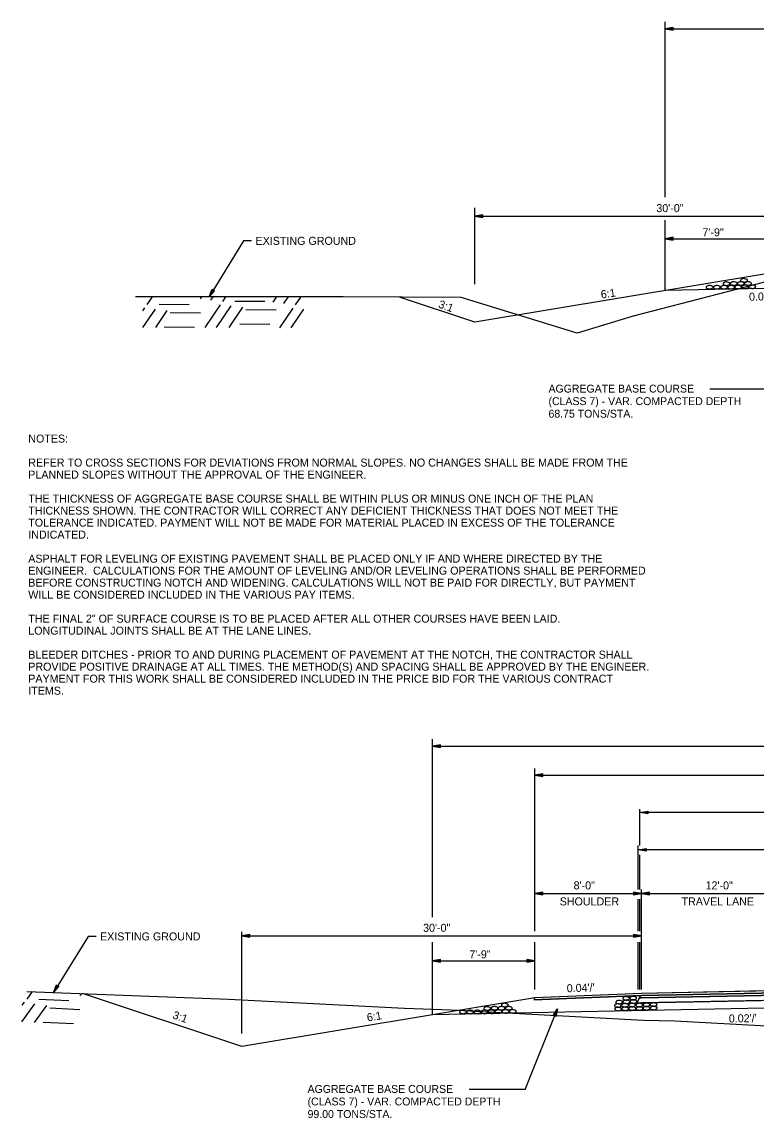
# Model space of a CAD drawing. Extents: x 1461846 to 1462006, y 1686171 to 1686805.
# Drawn here: x 1461850.2 to 1461905.3, y 1686719.1 to 1686801.3 of the extents above; entities that cross this region are included whole.
import ezdxf

# ---------------------------------------------------------------- set-up
doc = ezdxf.new("R2010")
doc.units = 0
for name, color, linetype in [('1', 7, 'Continuous'), ('19', 7, 'Continuous'), ('20', 7, 'Continuous'), ('R_Draft', 7, 'Continuous')]:
    doc.layers.add(name, color=color, linetype=linetype)

# ---------------------------------------------------------------- blocks, each defined once
blk = doc.blocks.new('ROCKS')
at = {"layer": '1'}
blk.add_spline([(0.013, 0.06), (0.053, 0.053), (0.107, 0.033), (0.133, 0.013), (0.133, -0.007), (0.12, -0.033), (0.107, -0.04), (0.073, -0.053), (0.033, -0.067), (0.013, -0.067), (-0.02, -0.06), (-0.06, -0.053), (-0.087, -0.047), (-0.113, -0.02), (-0.113, -0.007), (-0.107, 0.02), (-0.087, 0.033), (-0.067, 0.047), (-0.033, 0.053), (-0.02, 0.06), (0.013, 0.06)], degree=3, dxfattribs=at)

msp = doc.modelspace()

# ---------------------------------------------------------------- linework, layer by layer
at = {"layer": '19'}
for p, q in [((1461898.458, 1686788.158), (1461898.458, 1686801.288)), ((1461899.058, 1686800.872), (1461898.458, 1686800.767)), ((1461898.458, 1686800.767), (1461953.889, 1686800.767)), ((1461898.458, 1686800.767), (1461899.058, 1686800.662)), ((1461899.058, 1686800.817), (1461898.618, 1686800.782)), ((1461898.618, 1686800.752), (1461899.058, 1686800.712)), ((1461899.058, 1686800.662), (1461899.058, 1686800.872)), ((1461884.774, 1686786.831), (1461884.174, 1686786.726)), ((1461884.174, 1686786.726), (1461914.174, 1686786.726)), ((1461884.174, 1686786.726), (1461884.774, 1686786.621)), ((1461884.774, 1686786.776), (1461884.334, 1686786.741)), ((1461884.334, 1686786.711), (1461884.774, 1686786.671)), ((1461884.774, 1686786.621), (1461884.774, 1686786.831)), ((1461898.458, 1686781.149), (1461898.458, 1686786.426)), ((1461906.174, 1686782.435), (1461884.174, 1686778.769)), ((1461864.232, 1686780.674), (1461864.455, 1686781.241)), ((1461864.633, 1686781.131), (1461864.232, 1686780.674)), ((1461864.305, 1686780.815), (1461864.498, 1686781.209)), ((1461864.592, 1686781.152), (1461864.328, 1686780.804)), ((1461864.455, 1686781.241), (1461864.633, 1686781.131)), ((1461910.591, 1686781.392), (1461898.458, 1686781.149)), ((1461859.589, 1686780.092), (1461859.982, 1686780.674)), ((1461860.478, 1686780.129), (1461862.738, 1686780.103)), ((1461863.576, 1686780.517), (1461863.682, 1686780.667)), ((1461863.923, 1686778.369), (1461865.079, 1686780.087)), ((1461864.37, 1686780.423), (1461864.537, 1686780.667)), ((1461864.777, 1686778.369), (1461865.873, 1686779.994)), ((1461865.265, 1686780.329), (1461865.492, 1686780.667)), ((1461866.153, 1686780.356), (1461868.414, 1686780.34)), ((1461869.029, 1686780.265), (1461869.292, 1686780.659)), ((1461869.824, 1686780.171), (1461870.157, 1686780.659)), ((1461870.719, 1686780.077), (1461871.101, 1686780.65)), ((1461859.248, 1686779.625), (1461859.403, 1686779.85)), ((1461859.268, 1686778.376), (1461860.197, 1686779.757)), ((1461860.223, 1686778.376), (1461861.092, 1686779.662)), ((1461861.316, 1686779.498), (1461863.576, 1686779.471)), ((1461865.733, 1686778.369), (1461866.768, 1686779.899)), ((1461866.982, 1686779.726), (1461869.252, 1686779.708)), ((1461869.533, 1686778.361), (1461870.532, 1686779.835)), ((1461870.387, 1686778.362), (1461871.327, 1686779.741)), ((1461860.861, 1686778.42), (1461863.132, 1686778.402)), ((1461866.537, 1686778.657), (1461868.797, 1686778.63)), ((1461906.015, 1686773.763), (1461901.805, 1686773.763)), ((1461880.979, 1686734.152), (1461880.979, 1686747.499)), ((1461881.579, 1686747.084), (1461880.979, 1686746.979)), ((1461881.579, 1686746.874), (1461881.579, 1686747.084)), ((1461880.979, 1686746.979), (1461971.391, 1686746.979)), ((1461880.979, 1686746.979), (1461881.579, 1686746.874)), ((1461881.579, 1686747.029), (1461881.139, 1686746.994)), ((1461881.139, 1686746.964), (1461881.579, 1686746.924)), ((1461888.675, 1686733.114), (1461888.675, 1686745.306)), ((1461889.275, 1686744.911), (1461888.675, 1686744.806)), ((1461888.675, 1686744.806), (1461963.675, 1686744.806)), ((1461888.675, 1686744.806), (1461889.275, 1686744.701)), ((1461889.275, 1686744.856), (1461888.835, 1686744.821)), ((1461888.835, 1686744.791), (1461889.275, 1686744.751)), ((1461889.275, 1686744.701), (1461889.275, 1686744.911)), ((1461880.979, 1686726.84), (1461880.979, 1686732.284)), ((1461888.675, 1686728.743), (1461888.675, 1686732.284)), ((1461850.568, 1686728.011), (1461850.982, 1686728.578)), ((1461854.567, 1686728.292), (1461854.679, 1686728.437)), ((1461896.59, 1686728.273), (1461896.313, 1686727.72)), ((1461850.185, 1686726.308), (1461851.164, 1686727.654)), ((1461850.21, 1686727.557), (1461850.373, 1686727.776)), ((1461851.139, 1686726.273), (1461852.055, 1686727.527)), ((1461851.457, 1686728.016), (1461853.715, 1686727.908)), ((1461852.273, 1686727.355), (1461854.53, 1686727.246)), ((1461888.675, 1686728.123), (1461888.59, 1686727.953)), ((1461896.505, 1686728.103), (1461896.313, 1686727.72)), ((1461887.939, 1686721.25), (1461890.362, 1686727.3)), ((1461890.043, 1686726.783), (1461890.362, 1686727.3)), ((1461890.236, 1686726.704), (1461890.043, 1686726.783)), ((1461890.089, 1686726.765), (1461890.288, 1686727.158)), ((1461890.315, 1686727.148), (1461890.188, 1686726.727)), ((1461890.362, 1686727.3), (1461890.236, 1686726.704)), ((1461851.778, 1686726.294), (1461854.047, 1686726.194)), ((1461887.939, 1686721.25), (1461883.729, 1686721.25))]:
    msp.add_line(p, q, dxfattribs=at)
for points in [[(1461867.414, 1686784.873), (1461866.814, 1686784.873), (1461864.232, 1686780.674)], [(1461896.313, 1686727.72), (1461896.675, 1686727.734), (1461926.175, 1686728.324), (1461955.675, 1686727.734), (1461964.036, 1686727.4)], [(1461963.845, 1686727.783), (1461955.675, 1686728.109), (1461926.175, 1686728.699), (1461896.675, 1686728.109), (1461896.505, 1686728.103)]]:
    msp.add_lwpolyline(points, dxfattribs=at)
for points in [[(1461888.59, 1686727.953), (1461896.675, 1686728.276), (1461926.175, 1686728.866), (1461955.675, 1686728.276), (1461963.76, 1686727.953), (1461963.675, 1686728.123), (1461955.675, 1686728.443), (1461926.175, 1686729.033), (1461896.675, 1686728.443), (1461888.675, 1686728.123)], [(1461896.505, 1686728.103), (1461896.674, 1686728.109), (1461926.174, 1686728.699), (1461955.674, 1686728.109), (1461963.845, 1686727.783), (1461963.76, 1686727.953), (1461955.674, 1686728.276), (1461926.174, 1686728.866), (1461896.674, 1686728.276), (1461896.59, 1686728.273)]]:
    msp.add_lwpolyline(points, close=True, dxfattribs=at)
at = {"layer": '20'}
for p, q in [((1461884.174, 1686781.616), (1461884.174, 1686787.36)), ((1461899.058, 1686785.137), (1461898.458, 1686785.032)), ((1461898.458, 1686785.032), (1461906.174, 1686785.032)), ((1461898.458, 1686785.032), (1461899.058, 1686784.927)), ((1461899.058, 1686785.082), (1461898.618, 1686785.047)), ((1461898.618, 1686785.017), (1461899.058, 1686784.977)), ((1461899.058, 1686784.927), (1461899.058, 1686785.137)), ((1461896.545, 1686739.532), (1461896.545, 1686742.261)), ((1461896.545, 1686742.006), (1461897.145, 1686742.111)), ((1461897.145, 1686741.901), (1461896.545, 1686742.006)), ((1461963.801, 1686742.006), (1461896.545, 1686742.006)), ((1461896.705, 1686742.021), (1461897.145, 1686742.056)), ((1461897.145, 1686741.951), (1461896.705, 1686741.991)), ((1461897.145, 1686742.111), (1461897.145, 1686741.901)), ((1461896.413, 1686736.243), (1461896.413, 1686739.532)), ((1461896.413, 1686739.206), (1461897.013, 1686739.311)), ((1461963.933, 1686739.206), (1461896.413, 1686739.206)), ((1461897.013, 1686739.101), (1461896.413, 1686739.206)), ((1461896.545, 1686736.243), (1461896.545, 1686738.844)), ((1461896.573, 1686739.221), (1461897.013, 1686739.256)), ((1461897.013, 1686739.151), (1461896.573, 1686739.191)), ((1461897.013, 1686739.311), (1461897.013, 1686739.101)), ((1461896.413, 1686733.114), (1461896.413, 1686735.518)), ((1461896.545, 1686733.114), (1461896.545, 1686735.518)), ((1461896.413, 1686728.743), (1461896.413, 1686732.284)), ((1461896.545, 1686728.743), (1461896.545, 1686732.284)), ((1461881.579, 1686730.998), (1461880.979, 1686730.894)), ((1461880.979, 1686730.894), (1461888.675, 1686730.894)), ((1461880.979, 1686730.894), (1461881.579, 1686730.788)), ((1461881.579, 1686730.943), (1461881.139, 1686730.908)), ((1461881.139, 1686730.878), (1461881.579, 1686730.838)), ((1461881.579, 1686730.788), (1461881.579, 1686730.998)), ((1461888.075, 1686730.999), (1461888.075, 1686730.789)), ((1461888.675, 1686730.894), (1461888.075, 1686730.999)), ((1461888.515, 1686730.909), (1461888.075, 1686730.944)), ((1461888.075, 1686730.789), (1461888.675, 1686730.894)), ((1461888.075, 1686730.839), (1461888.515, 1686730.879))]:
    msp.add_line(p, q, dxfattribs=at)
at = {"layer": 'R_Draft'}
for p, q in [((1461884.174, 1686778.769), (1461878.518, 1686780.654)), ((1461889.275, 1686736.048), (1461888.675, 1686735.943)), ((1461888.675, 1686735.943), (1461896.675, 1686735.943)), ((1461888.675, 1686735.943), (1461889.275, 1686735.838)), ((1461889.275, 1686735.993), (1461888.835, 1686735.958)), ((1461888.835, 1686735.928), (1461889.275, 1686735.888)), ((1461889.275, 1686735.838), (1461889.275, 1686736.048)), ((1461896.075, 1686736.048), (1461896.075, 1686735.838)), ((1461896.675, 1686735.943), (1461896.075, 1686736.048)), ((1461896.515, 1686735.958), (1461896.075, 1686735.993)), ((1461896.075, 1686735.838), (1461896.675, 1686735.943)), ((1461896.075, 1686735.888), (1461896.515, 1686735.928)), ((1461896.675, 1686728.743), (1461896.675, 1686736.243)), ((1461897.275, 1686736.048), (1461896.675, 1686735.943)), ((1461897.275, 1686736.048), (1461896.675, 1686735.943)), ((1461896.675, 1686735.943), (1461897.275, 1686735.838)), ((1461896.675, 1686735.943), (1461908.675, 1686735.943)), ((1461896.675, 1686735.943), (1461897.275, 1686735.838)), ((1461897.275, 1686735.993), (1461896.835, 1686735.958)), ((1461897.275, 1686735.993), (1461896.835, 1686735.958)), ((1461896.835, 1686735.928), (1461897.275, 1686735.888)), ((1461896.835, 1686735.928), (1461897.275, 1686735.888)), ((1461897.275, 1686735.838), (1461897.275, 1686736.048)), ((1461897.275, 1686735.838), (1461897.275, 1686736.048)), ((1461866.675, 1686725.439), (1461866.675, 1686733.064)), ((1461867.275, 1686732.869), (1461866.675, 1686732.764)), ((1461866.675, 1686732.764), (1461896.675, 1686732.764)), ((1461866.675, 1686732.764), (1461867.275, 1686732.659)), ((1461867.275, 1686732.814), (1461866.835, 1686732.779)), ((1461866.835, 1686732.749), (1461867.275, 1686732.709)), ((1461867.275, 1686732.659), (1461867.275, 1686732.869)), ((1461896.075, 1686732.869), (1461896.075, 1686732.659)), ((1461896.675, 1686732.764), (1461896.075, 1686732.869)), ((1461896.515, 1686732.779), (1461896.075, 1686732.814)), ((1461896.075, 1686732.659), (1461896.675, 1686732.764)), ((1461896.075, 1686732.709), (1461896.515, 1686732.749)), ((1461852.562, 1686728.518), (1461852.786, 1686729.084)), ((1461852.963, 1686728.975), (1461852.562, 1686728.518)), ((1461852.636, 1686728.659), (1461852.829, 1686729.052)), ((1461852.923, 1686728.996), (1461852.659, 1686728.647)), ((1461852.786, 1686729.084), (1461852.963, 1686728.975)), ((1461926.175, 1686729.033), (1461896.675, 1686728.443)), ((1461866.675, 1686724.456), (1461854.74, 1686728.434)), ((1461896.675, 1686728.276), (1461888.59, 1686727.953)), ((1461896.675, 1686728.443), (1461888.675, 1686728.123)), ((1461926.175, 1686728.866), (1461896.675, 1686728.276)), ((1461926.175, 1686728.699), (1461896.675, 1686728.109)), ((1461926.175, 1686728.324), (1461896.675, 1686727.734)), ((1461888.675, 1686728.123), (1461866.675, 1686724.456)), ((1461926.175, 1686727.741), (1461880.959, 1686726.837)), ((1461896.675, 1686727.734), (1461896.313, 1686727.72)), ((1461896.675, 1686728.109), (1461896.505, 1686728.103))]:
    msp.add_line(p, q, dxfattribs=at)
for points in [[(1461963.023, 1686774.822), (1461938.674, 1686781.973), (1461934.591, 1686782.66), (1461933.001, 1686782.563), (1461913.998, 1686782.421), (1461910.591, 1686782.445), (1461906.674, 1686781.973), (1461896.057, 1686779.215), (1461891.841, 1686777.956), (1461883.145, 1686780.632), (1461874.28, 1686780.674), (1461858.704, 1686780.674)], [(1461855.745, 1686732.717), (1461855.145, 1686732.717), (1461852.562, 1686728.518)], [(1461850.553, 1686728.595), (1461865.683, 1686728.014), (1461878.883, 1686727.333), (1461882.383, 1686727.222), (1461896.83, 1686726.446), (1461899.18, 1686726.39), (1461913.404, 1686725.61), (1461923.498, 1686724.971), (1461934.669, 1686724.333), (1461947.841, 1686723.499), (1461965.496, 1686722.968), (1461965.961, 1686722.96)]]:
    msp.add_lwpolyline(points, dxfattribs=at)

# ---------------------------------------------------------------- block references
at = {"layer": '19', "xscale": 2.061136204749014, "yscale": 2.061136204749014}
for p in [(1461903.025, 1686781.664), (1461903.567, 1686781.68), (1461904.101, 1686781.68), (1461904.338, 1686781.919), (1461904.643, 1686781.68), (1461904.96, 1686781.438), (1461901.762, 1686781.401), (1461902.301, 1686781.401), (1461902.845, 1686781.401), (1461903.372, 1686781.401), (1461903.903, 1686781.415), (1461904.427, 1686781.428), (1461895.496, 1686728.081), (1461896.025, 1686728.1), (1461885.076, 1686727.324), (1461885.618, 1686727.34), (1461886.152, 1686727.34), (1461886.389, 1686727.579), (1461886.694, 1686727.34), (1461894.881, 1686727.542), (1461894.898, 1686727.281), (1461894.98, 1686727.801), (1461895.414, 1686727.561), (1461895.431, 1686727.3), (1461895.513, 1686727.82), (1461895.944, 1686727.581), (1461895.961, 1686727.319), (1461896.042, 1686727.839), (1461896.49, 1686727.578), (1461896.507, 1686727.316), (1461897.019, 1686727.597), (1461897.036, 1686727.335), (1461897.549, 1686727.616), (1461897.565, 1686727.354), (1461883.259, 1686727.061), (1461883.797, 1686727.061), (1461884.341, 1686727.061), (1461884.868, 1686727.061), (1461885.399, 1686727.075), (1461885.923, 1686727.088), (1461886.457, 1686727.098), (1461887.002, 1686727.107)]:
    msp.add_blockref('ROCKS', p, dxfattribs=at)

# ---------------------------------------------------------------- texts
at = {"layer": '19'}
for s, p in [('AGGREGATE BASE COURSE', (1461889.693, 1686773.497)), ('(CLASS 7) - VAR. COMPACTED DEPTH', (1461889.693, 1686772.557)), ('68.75 TONS/STA.', (1461889.693, 1686771.617)), ('AGGREGATE BASE COURSE', (1461871.617, 1686720.985)), ('(CLASS 7) - VAR. COMPACTED DEPTH', (1461871.617, 1686720.045)), ('99.00 TONS/STA.', (1461871.617, 1686719.105))]:
    msp.add_text(s, height=0.59001, rotation=360, dxfattribs=at).set_placement(p)
at = {"layer": 'R_Draft'}
for s, rotation, p in [('30\'-0"', 360, (1461897.783, 1686787.026)), ('7\'-9"', 360, (1461901.241, 1686785.215)), ('EXISTING GROUND', 360, (1461867.714, 1686784.573)), ('6:1', 8.61713, (1461893.662, 1686780.542)), ("0.02'/'", 1.14576, (1461904.742, 1686780.38)), ('3:1', 340.49426, (1461881.387, 1686779.885)), ('8\'-0"', 360, (1461891.576, 1686736.243)), ('12\'-0"', 360, (1461901.477, 1686736.243)), ('SHOULDER', 360, (1461890.532, 1686735.043)), ('TRAVEL LANE', 360, (1461899.675, 1686735.043)), ('30\'-0"', 360, (1461880.283, 1686733.064)), ('EXISTING GROUND', 360, (1461856.045, 1686732.417)), ('7\'-9"', 360, (1461883.752, 1686731.076)), ("0.04'/'", 2.16019, (1461891.073, 1686728.526)), ('3:1', 340.49426, (1461861.444, 1686726.589)), ('6:1', 9.46232, (1461876.117, 1686726.33)), ("0.02'/'", 1.14576, (1461903.227, 1686726.257))]:
    msp.add_text(s, height=0.6, rotation=rotation, dxfattribs=at).set_placement(p)
for s, p in [('NOTES:', (1461850.662, 1686769.745)), ('REFER TO CROSS SECTIONS FOR DEVIATIONS FROM NORMAL SLOPES. NO CHANGES SHALL BE MADE FROM THE ', (1461850.662, 1686767.945)), ('PLANNED SLOPES WITHOUT THE APPROVAL OF THE ENGINEER.', (1461850.662, 1686767.045)), ('THE THICKNESS OF AGGREGATE BASE COURSE SHALL BE WITHIN PLUS OR MINUS ONE INCH OF THE PLAN ', (1461850.662, 1686765.245)), ('THICKNESS SHOWN. THE CONTRACTOR WILL CORRECT ANY DEFICIENT THICKNESS THAT DOES NOT MEET THE ', (1461850.662, 1686764.345)), ('TOLERANCE INDICATED. PAYMENT WILL NOT BE MADE FOR MATERIAL PLACED IN EXCESS OF THE TOLERANCE ', (1461850.662, 1686763.445)), ('INDICATED.', (1461850.662, 1686762.545)), ('ASPHALT FOR LEVELING OF EXISTING PAVEMENT SHALL BE PLACED ONLY IF AND WHERE DIRECTED BY THE ', (1461850.662, 1686760.745)), ('ENGINEER.  CALCULATIONS FOR THE AMOUNT OF LEVELING AND/OR LEVELING OPERATIONS SHALL BE PERFORMED ', (1461850.662, 1686759.845)), ('BEFORE CONSTRUCTING NOTCH AND WIDENING. CALCULATIONS WILL NOT BE PAID FOR DIRECTLY, BUT PAYMENT ', (1461850.662, 1686758.945)), ('WILL BE CONSIDERED INCLUDED IN THE VARIOUS PAY ITEMS.', (1461850.662, 1686758.045)), ('THE FINAL 2" OF SURFACE COURSE IS TO BE PLACED AFTER ALL OTHER COURSES HAVE BEEN LAID. ', (1461850.662, 1686756.245)), ('LONGITUDINAL JOINTS SHALL BE AT THE LANE LINES.', (1461850.662, 1686755.345)), ('BLEEDER DITCHES - PRIOR TO AND DURING PLACEMENT OF PAVEMENT AT THE NOTCH, THE CONTRACTOR SHALL ', (1461850.662, 1686753.545)), ('PROVIDE POSITIVE DRAINAGE AT ALL TIMES. THE METHOD(S) AND SPACING SHALL BE APPROVED BY THE ENGINEER. ', (1461850.662, 1686752.645)), ('PAYMENT FOR THIS WORK SHALL BE CONSIDERED INCLUDED IN THE PRICE BID FOR THE VARIOUS CONTRACT ', (1461850.662, 1686751.745)), ('ITEMS.', (1461850.662, 1686750.845))]:
    msp.add_text(s, height=0.6, dxfattribs=at).set_placement(p)

doc.saveas('drawing.dxf')
